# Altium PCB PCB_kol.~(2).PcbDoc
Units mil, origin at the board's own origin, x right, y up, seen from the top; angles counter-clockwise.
Board outline 2952.76 x 2952.76 mil, 4 copper layers (Top Layer, Mid 1 - POWER, Mid 2 - GND, Bottom Layer), stack 61.89 mil thick; 6 components, 16 nets, 136 pads, 7 vias.
Unrouted connection lines stored in the file: 1.
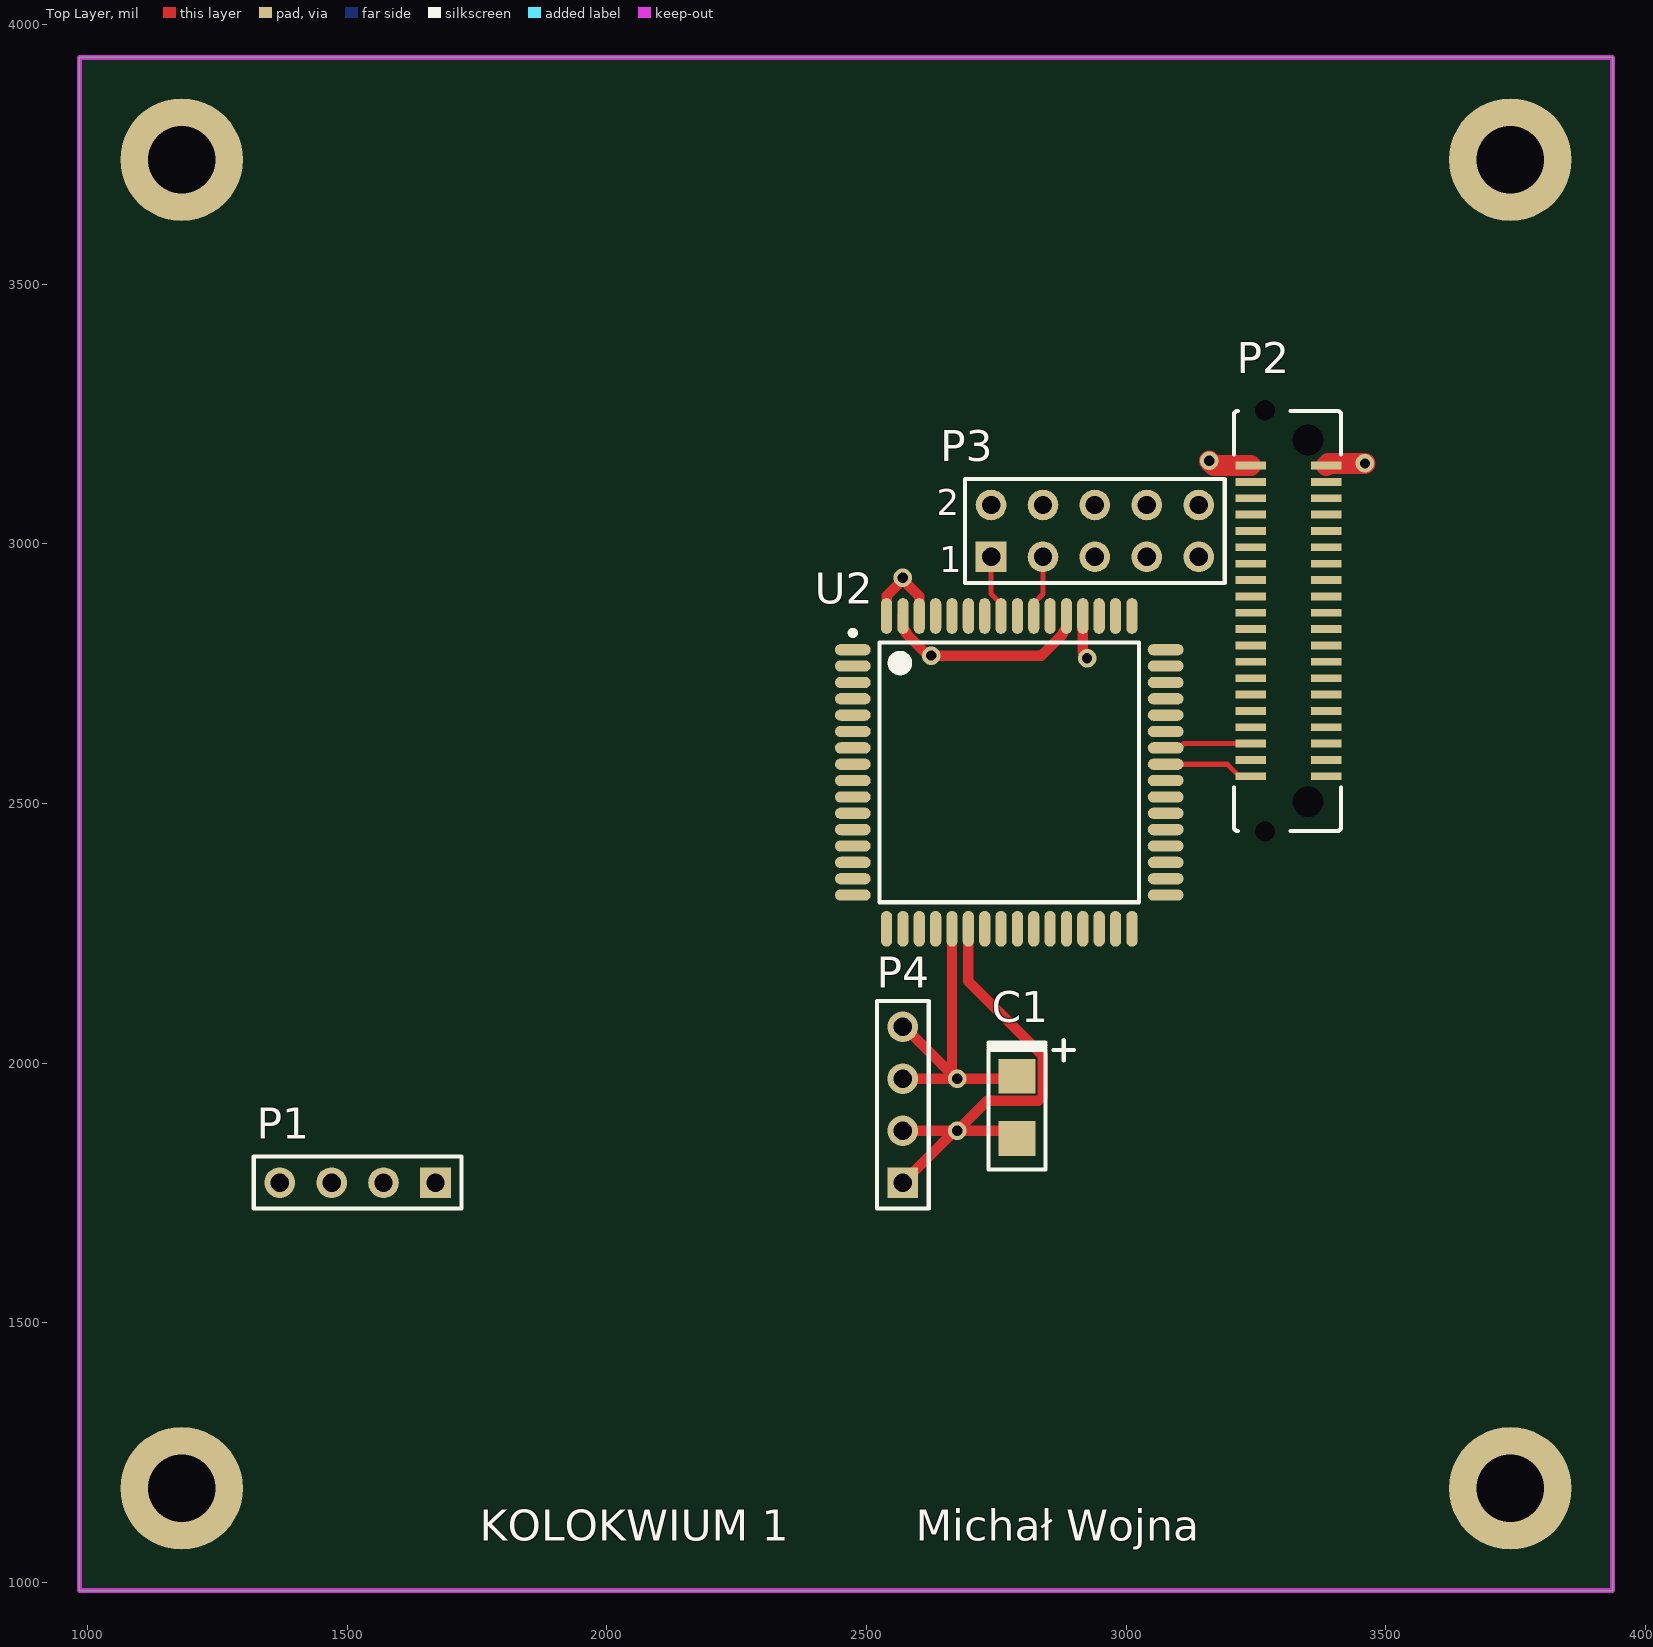
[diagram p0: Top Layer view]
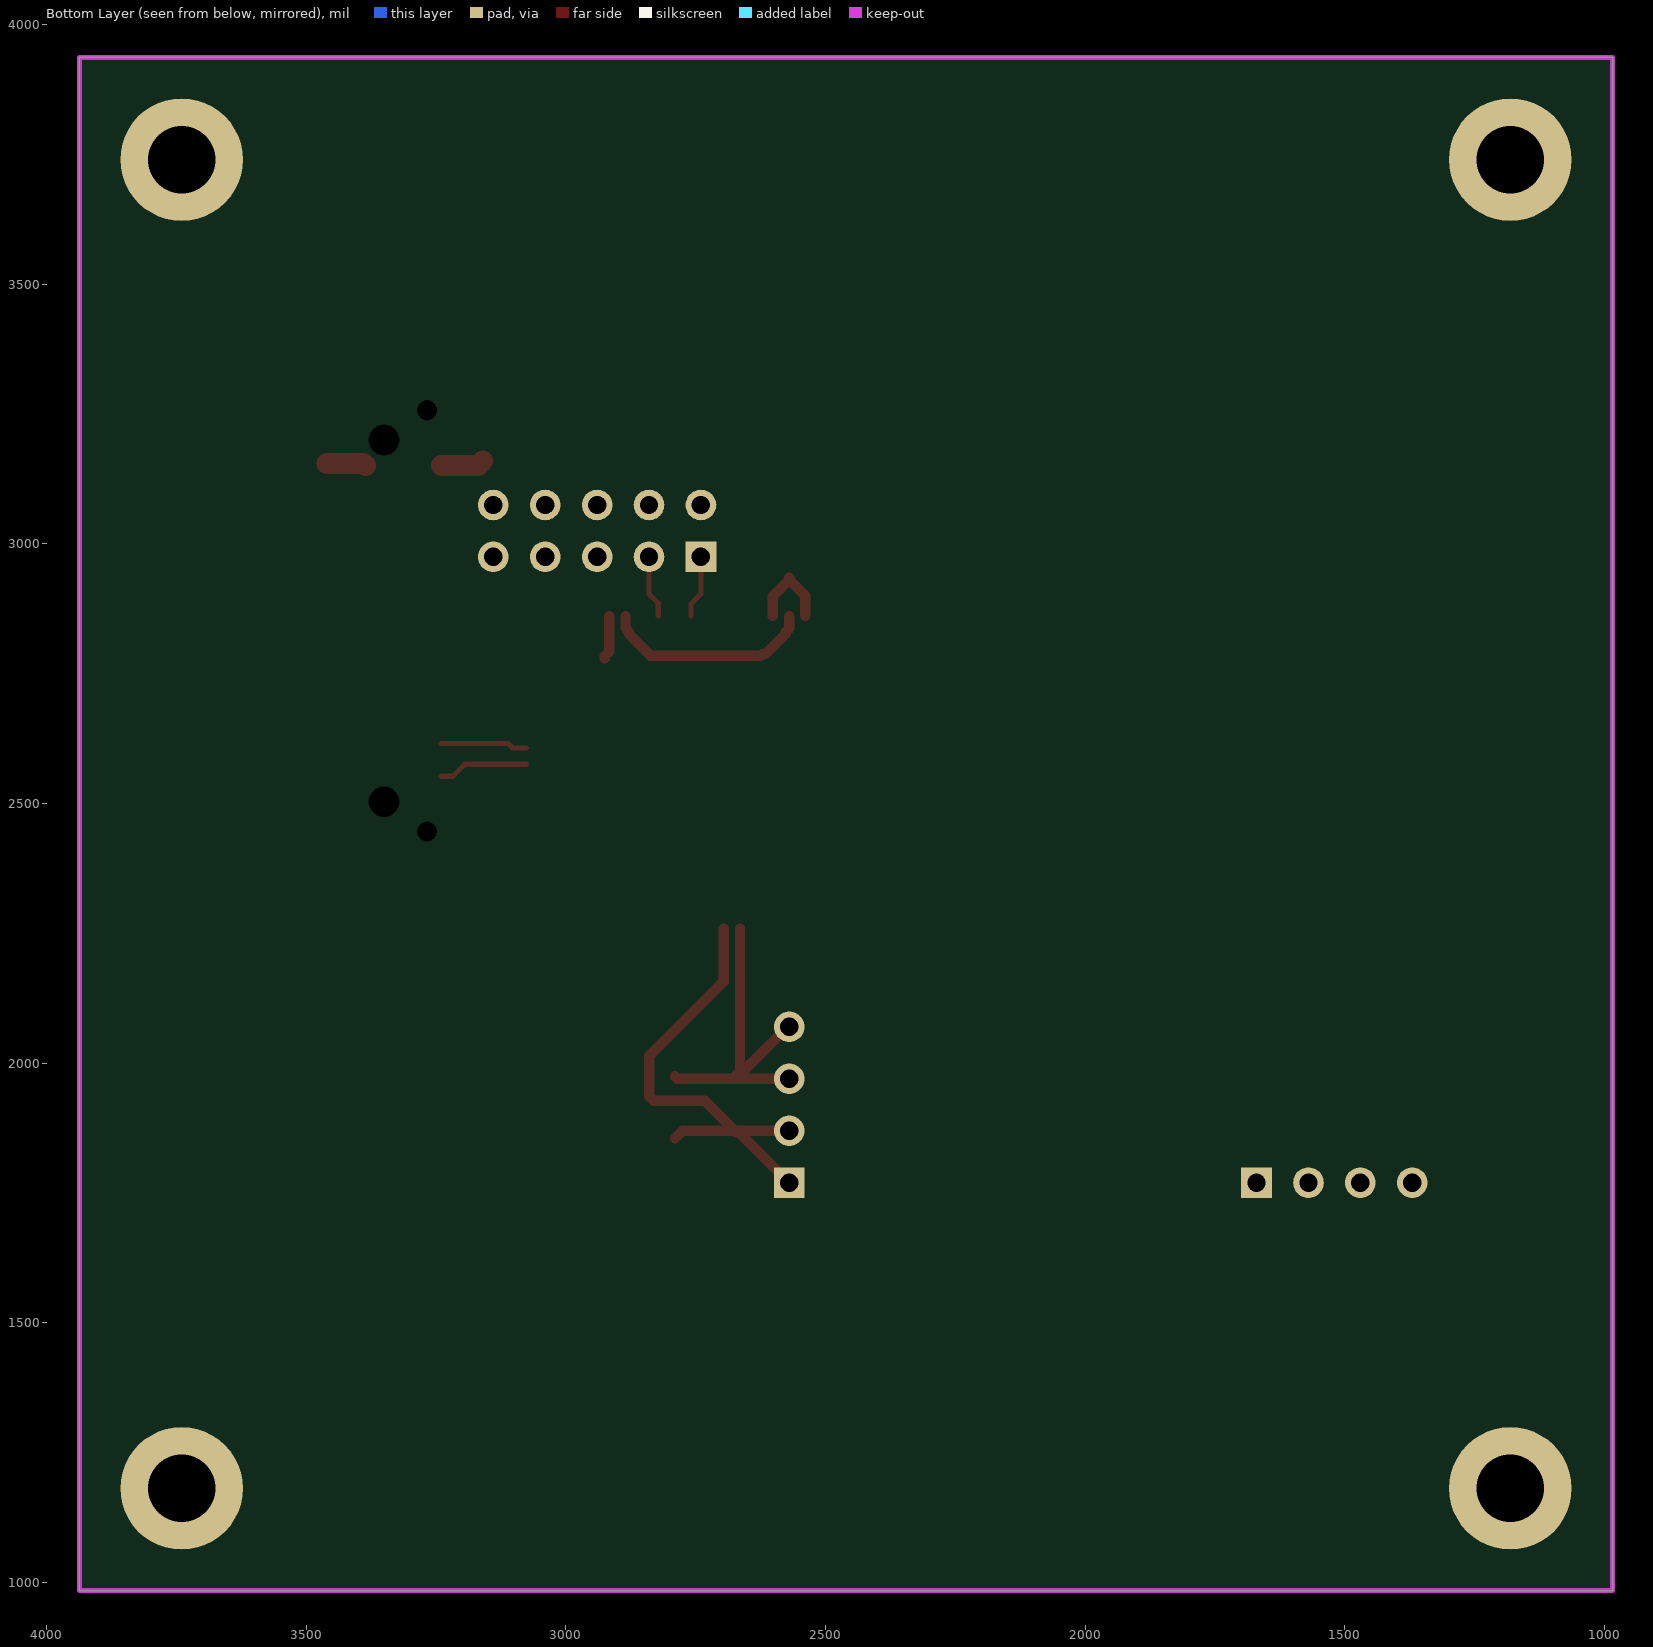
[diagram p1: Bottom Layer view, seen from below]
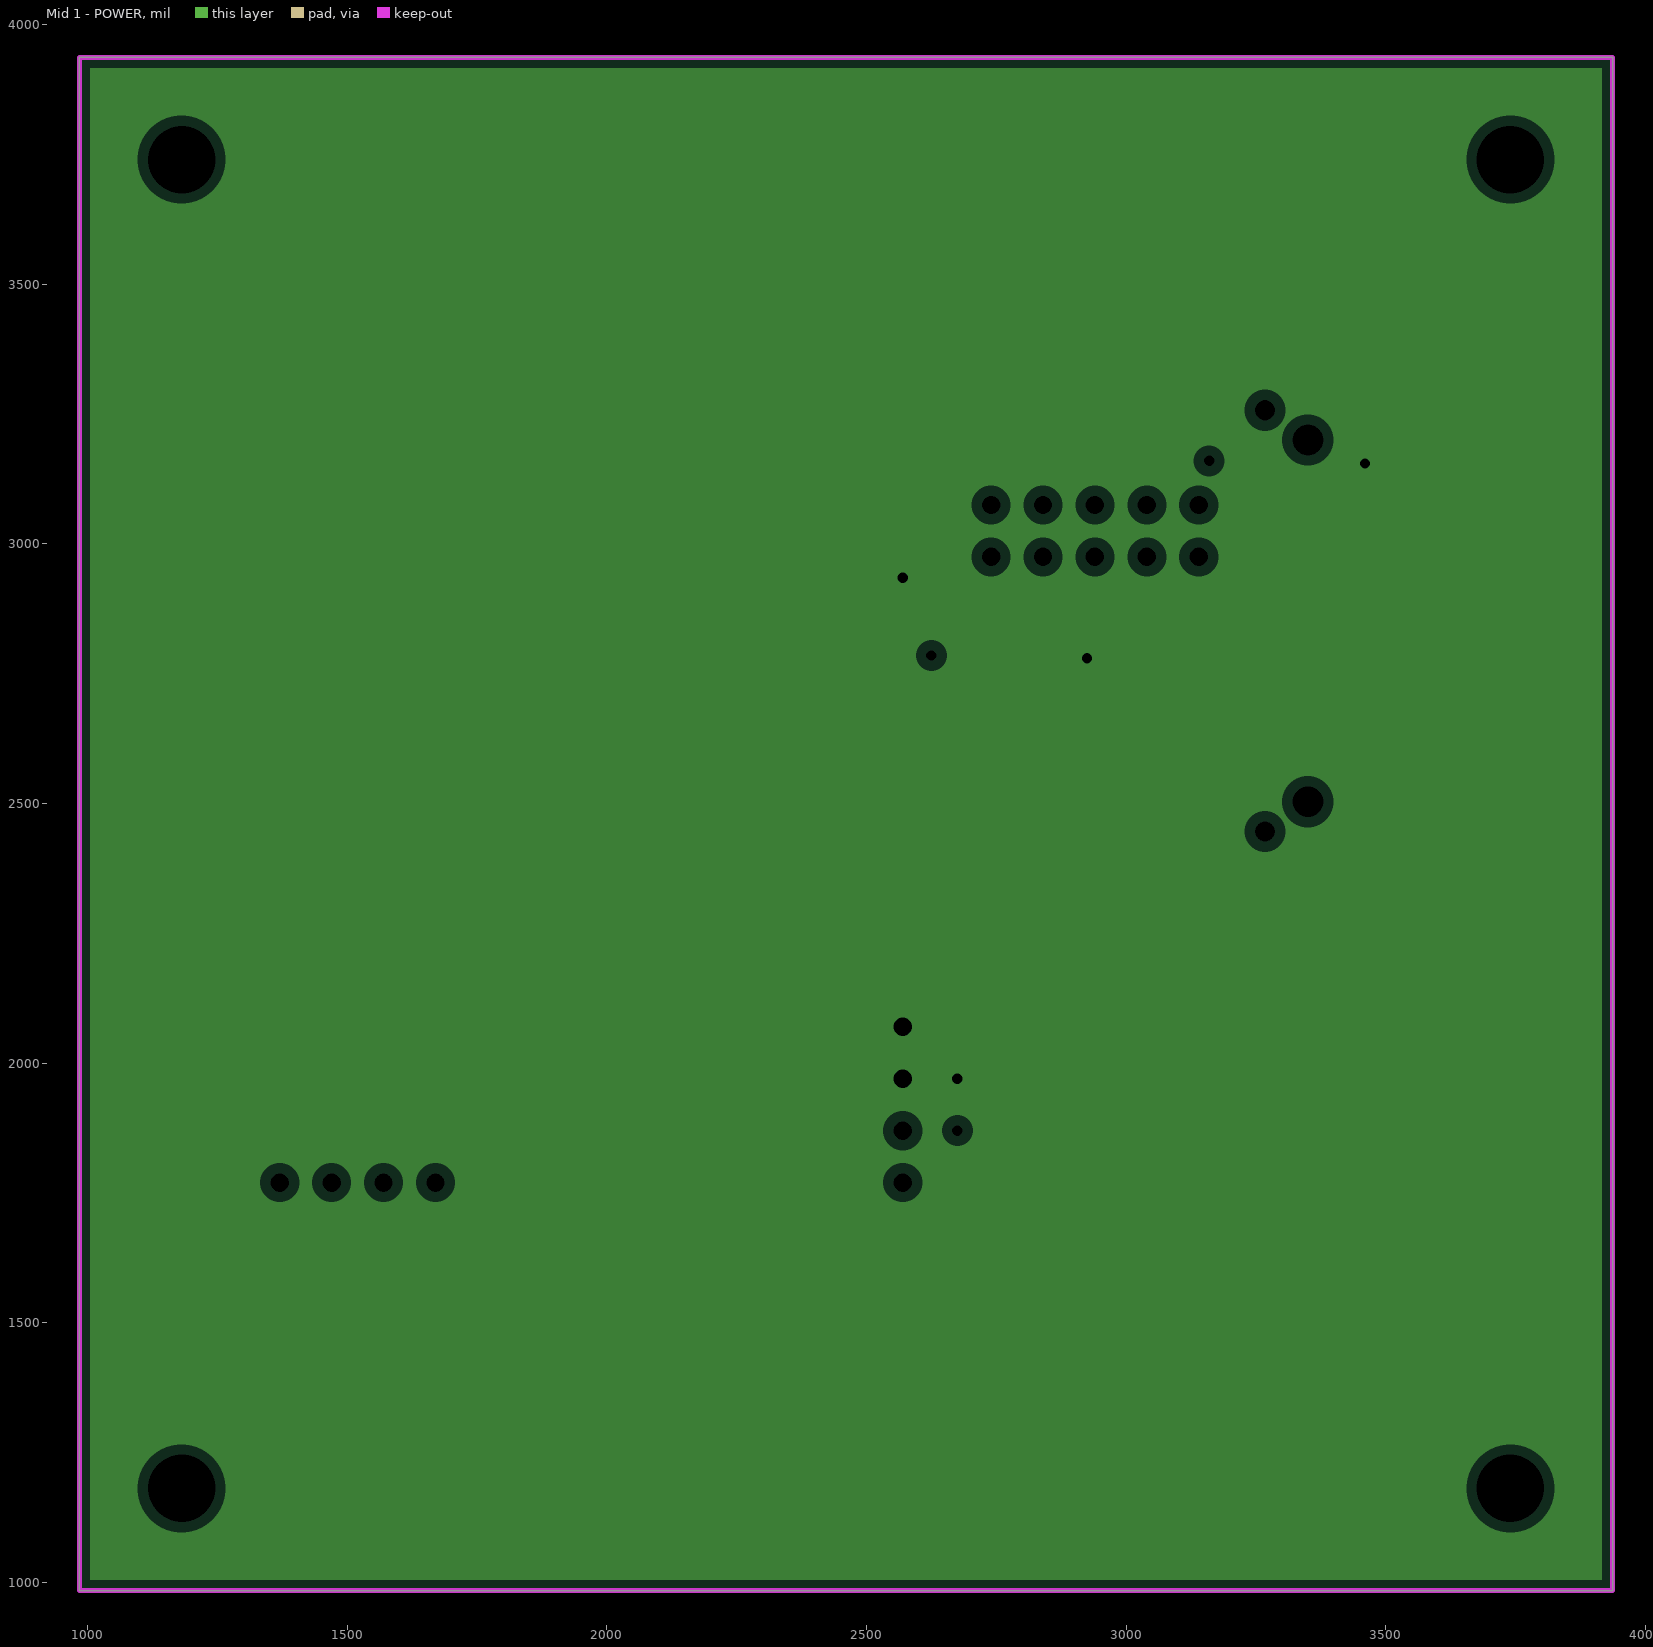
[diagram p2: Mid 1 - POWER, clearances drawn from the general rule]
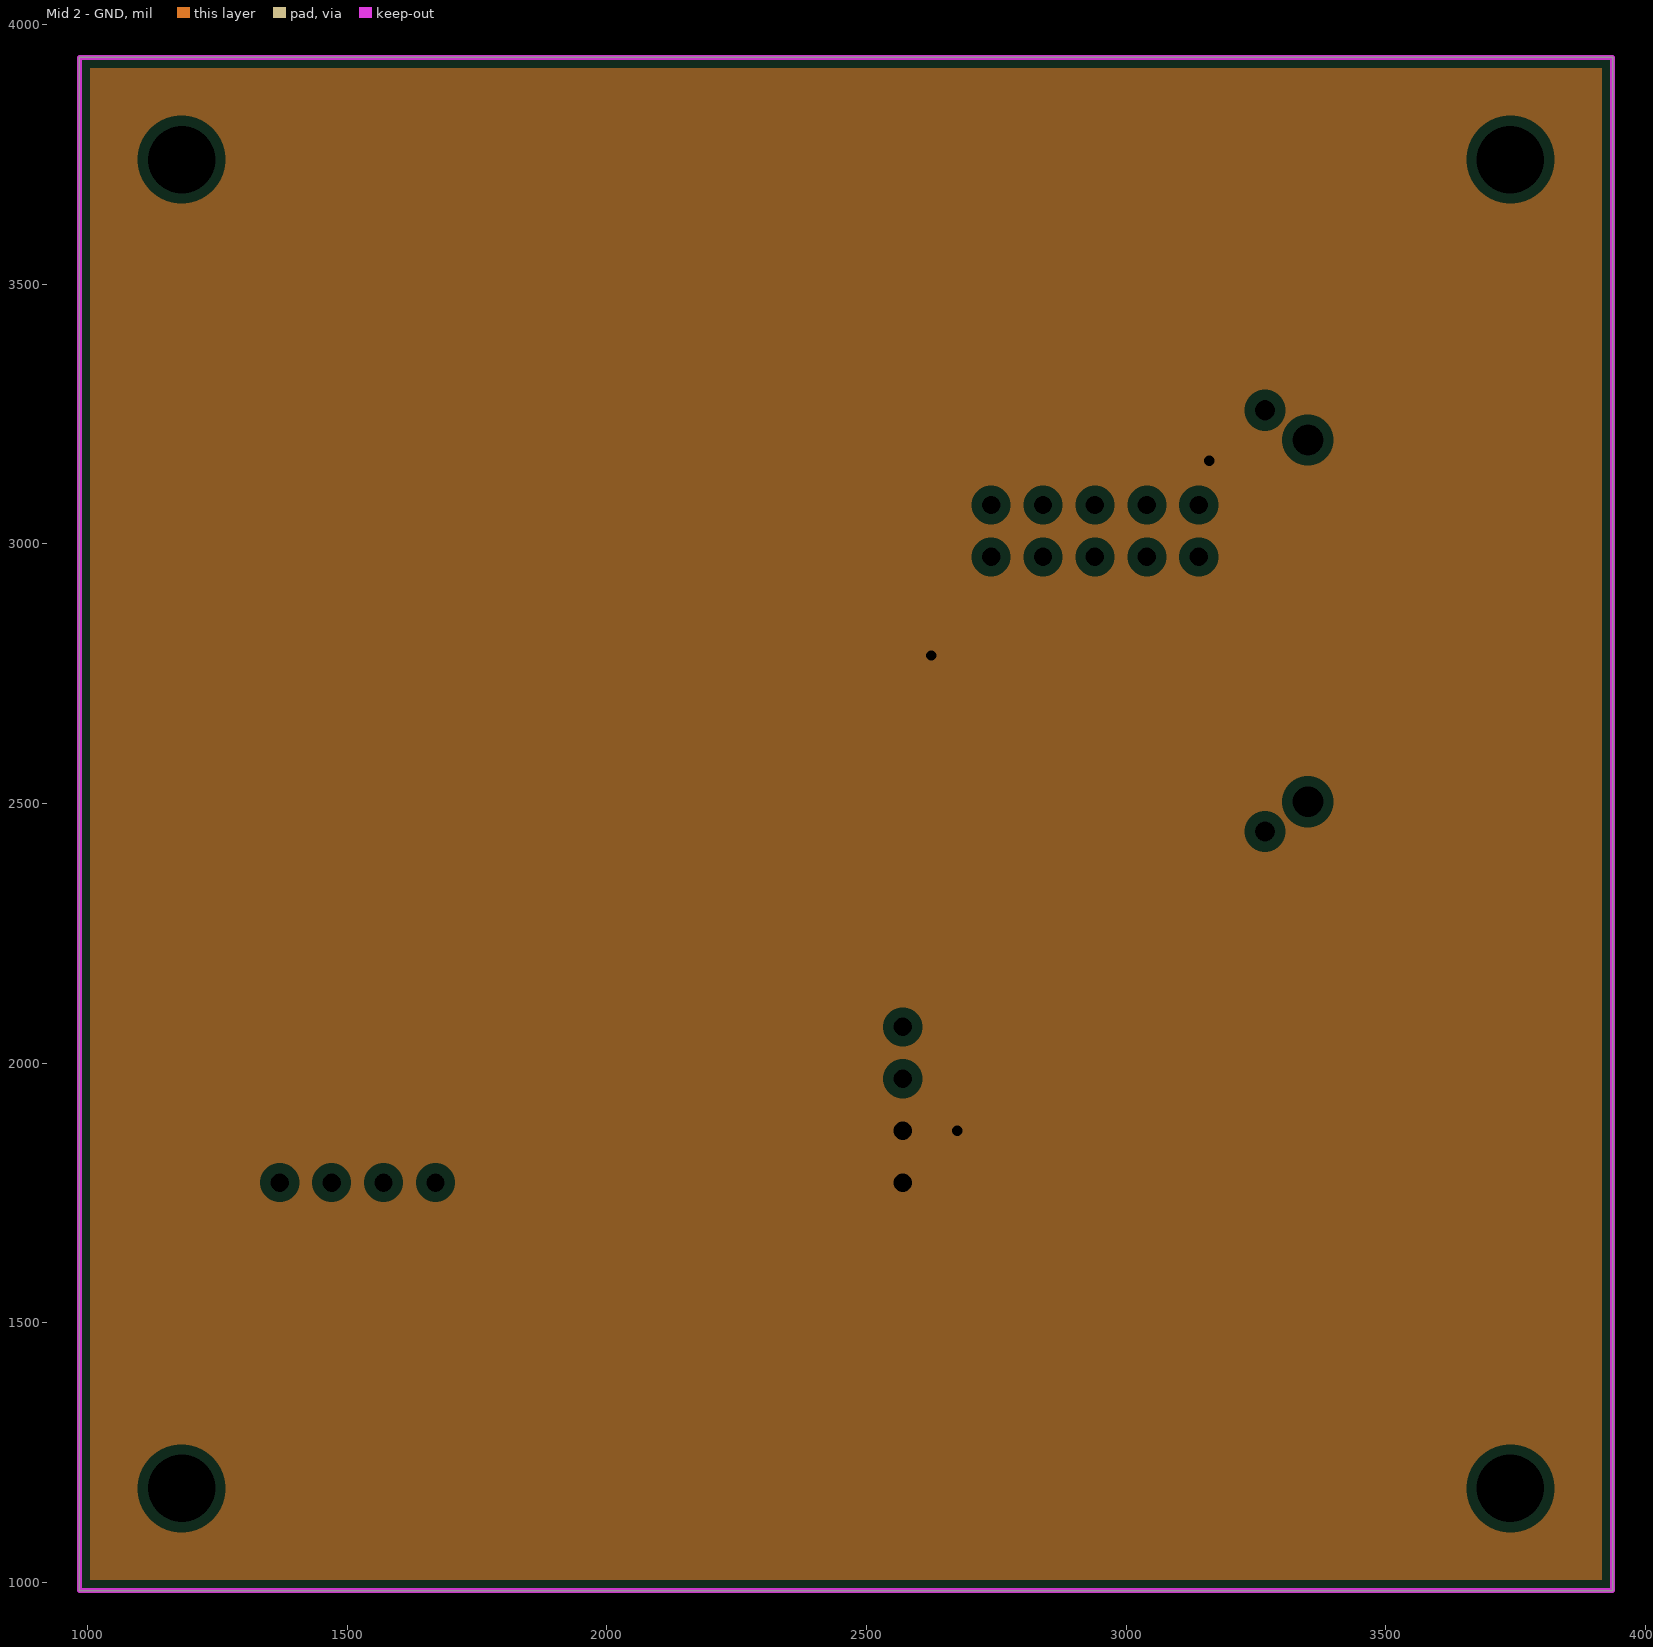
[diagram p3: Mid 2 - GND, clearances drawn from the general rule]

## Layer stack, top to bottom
Top Solder: solder mask 0.4, Solder Resist, Dk 3.5
Top Layer: signal copper 0.7087
Dielectric 1: prepreg 15, Isola DE 104ML, Dk 3.97
Mid 1 - POWER: plane copper 1.378, net 5V0
Dielectric 2: core 27.7165, Isola DE 104ML, Dk 3.97
Mid 2 - GND: plane copper 1.378, net GND
Dielectric 3: prepreg 15, Isola DE 104ML, Dk 3.97
Bottom Layer: signal copper 0.7087
Bottom Solder: solder mask 0.4, Solder Resist, Dk 3.5

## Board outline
984.25,984.25 3937.01,984.25 3937.01,3937.01 984.25,3937.01

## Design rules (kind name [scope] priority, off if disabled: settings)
Clearance [All] p1: gap=4 ignorepadtopadclearanceinfootprint=TRUE
HoleSize [All] p1: absolutevalues=TRUE maxlimit=130 minlimit=1 maxpercent=80.000 minpercent=20.000
MinimumSolderMaskSliver [All] p1: minsoldermaskwidth=4
PlaneClearance [All] p1: clearance=20
PlaneConnect [All] p1: planeconnectstyle=Relief reliefexpansion=20 reliefentries=4 reliefconductorwidth=10 reliefairgap=10
PolygonConnect [All] p1: connectstyle=Relief reliefconductorwidth=10 reliefentries=4 polygonreliefangle="90 Angle" airgapwidth=10
RoutingVias [All] p1: holewidth=28 width=50 viastyle="Through Hole" minholewidth=28 minwidth=50 maxholewidth=28 maxwidth=50
SolderMaskExpansion [All] p1: expansion=2 istentingtop=FALSE
SupplyNets "Schematic Supply Nets_1" [InNet('5V0')] p1: voltage=0.000
SupplyNets "Schematic Supply Nets" [InNet('GND')] p2: voltage=0.000
Width gnd&5v0 [(InNet('5V0') OR InNet('GND'))] p1: maxlimit=100 minlimit=20 preferedwidth=40
Width Width_1 [All] p2: maxlimit=10 minlimit=10 preferedwidth=10
26 further rules are at their usual default settings.

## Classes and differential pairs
component class Schemat_top: P1 P2 P4
component class U_Processor: C1 C? U2

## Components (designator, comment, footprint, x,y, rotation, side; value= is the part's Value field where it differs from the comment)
C1 "22u" VJ_Tantalum_A 2790,1915 r270 top
P1 "Header 4" HDR1X4 1670,1770 r180 top
P2 "SAMTEC LSEM 40-pin" LSEM-120-03.0-L-DV-A-N-K-TR 3312.83,2851.73 r90 top
P3 "Header 5X2" HDR2X5 2740,2975 r0 top
P4 "Header 4" HDR1X4 2570,1770 r90 top
U2 "ATmega128-16AU" 64A_N 2775,2560 r0 top

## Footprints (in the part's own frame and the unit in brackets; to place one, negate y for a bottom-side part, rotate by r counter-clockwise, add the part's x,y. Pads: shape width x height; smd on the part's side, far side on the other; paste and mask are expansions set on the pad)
64A_N [mm] "Thin QFP, 64-Leads, Body 14x14mm, Pitch 0.8mm, IPC Medium Density"
  oval 1.75x0.55 smd: 1(-7.65,6) 2(-7.65,5.2) 3(-7.65,4.4) 4(-7.65,3.6) 5(-7.65,2.8) 6(-7.65,2) 7(-7.65,1.2) 8(-7.65,0.4) 9(-7.65,-0.4) 10(-7.65,-1.2) 11(-7.65,-2) 12(-7.65,-2.8) 13(-7.65,-3.6) 14(-7.65,-4.4) 15(-7.65,-5.2) 16(-7.65,-6) 33(7.65,-6) 34(7.65,-5.2) 35(7.65,-4.4) 36(7.65,-3.6) 37(7.65,-2.8) 38(7.65,-2) 39(7.65,-1.2) 40(7.65,-0.4) 41(7.65,0.4) 42(7.65,1.2) 43(7.65,2) 44(7.65,2.8) 45(7.65,3.6) 46(7.65,4.4) 47(7.65,5.2) 48(7.65,6)
  oval 0.55x1.75 smd: 17(-6,-7.65) 18(-5.2,-7.65) 19(-4.4,-7.65) 20(-3.6,-7.65) 21(-2.8,-7.65) 22(-2,-7.65) 23(-1.2,-7.65) 24(-0.4,-7.65) 25(0.4,-7.65) 26(1.2,-7.65) 27(2,-7.65) 28(2.8,-7.65) 29(3.6,-7.65) 30(4.4,-7.65) 31(5.2,-7.65) 32(6,-7.65) 49(6,7.65) 50(5.2,7.65) 51(4.4,7.65) 52(3.6,7.65) 53(2.8,7.65) 54(2,7.65) 55(1.2,7.65) 56(0.4,7.65) 57(-0.4,7.65) 58(-1.2,7.65) 59(-2,7.65) 60(-2.8,7.65) 61(-3.6,7.65) 62(-4.4,7.65) 63(-5.2,7.65) 64(-6,7.65)
  silkscreen extent -7.77,-6.35 6.35,6.95, body extent -7,-7 7,7, height 1.2
HDR1X4 [mm] "Connector; Header; 4 Position"
  rect 1.5x1.5 hole 0.9: 1(0,0)
  round 1.5 hole 0.9: 2(2.54,0) 3(5.08,0) 4(7.62,0)
  silkscreen extent -1.27,-1.27 8.89,1.27
HDR2X5 [mm] "Connector; Header; 5x2 Position"
  rect 1.5x1.5 hole 0.9: 1(0,0)
  round 1.5 hole 0.9: 2(0,2.54) 3(2.54,0) 4(2.54,2.54) 5(5.08,0) 6(5.08,2.54) 7(7.62,0) 8(7.62,2.54) 9(10.16,0) 10(10.16,2.54)
  silkscreen extent -1.27,-1.27 11.43,3.81
LSEM-120-03.0-L-DV-A-N-K-TR [mm] "LSEM 0.8mm Razor Beam Hermaphroditic Connector 40-pin"
  round 0 hole 1 unplated: 0(-10.3,1.15) 0(10.3,1.15)
  round 2 on Top Paste paste+2: 0(-10.3,1.15) 0(10.3,1.15)
  round 2.1 on Top Solder paste+2: 0(-10.3,1.15) 0(10.3,1.15)
  round 0 hole 1.5 unplated: 0(-8.85,-0.95) 0(8.85,-0.95)
  rect 0.38x1.5 smd: 1(7.6,-1.85) 2(7.6,1.85) 3(6.8,-1.85) 4(6.8,1.85) 5(6,-1.85) 6(6,1.85) 7(5.2,-1.85) 8(5.2,1.85) 9(4.4,-1.85) 10(4.4,1.85) 11(3.6,-1.85) 12(3.6,1.85) 13(2.8,-1.85) 14(2.8,1.85) 15(2,-1.85) 16(2,1.85) 17(1.2,-1.85) 18(1.2,1.85) 19(0.4,-1.85) 20(0.4,1.85) 21(-0.4,-1.85) 22(-0.4,1.85) 23(-1.2,-1.85) 24(-1.2,1.85) 25(-2,-1.85) 26(-2,1.85) 27(-2.8,-1.85) 28(-2.8,1.85) 29(-3.6,-1.85) 30(-3.6,1.85) 31(-4.4,-1.85) 32(-4.4,1.85) 33(-5.2,-1.85) 34(-5.2,1.85) 35(-6,-1.85) 36(-6,1.85) 37(-6.8,-1.85) 38(-6.8,1.85) 39(-7.6,-1.85) 40(-7.6,1.85)
  silkscreen extent -10.28,-2.57 10.28,2.68, body extent -10.2,-2.7 10.2,2.8, height 4.58
VJ_Tantalum_A [mm]
  rect 1.7x1.8 smd: 1(-1.525,0) 2(1.525,0)
  silkscreen extent -3.3,-1.4 3.05,2.79, body extent -1.85,-0.89 1.85,0.89, height 1.6

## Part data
C1: library part Capacitor_polarized, Manufacturer=VJ, Part Number=293D223X9016D2TE3, Rated Voltage=16V, Tolerance=10%
P1 P4: "Header, 4-Pin"
P2: "Component desciption", Manufacture=SAMTEC, Part Number=LSEM-120-03.0-L-DV-A-N-K-TR, Supplier Part Number 1=2433813
P3: "Header, 5-Pin, Dual row"
U2: "8-bit AVR Microcontroller, 4.5-5.5V, 128KB Flash, 4KB EEPROM, 4KB SRAM, 64-pin TQFP, Industrial Grade (-40°C to 85°C)"

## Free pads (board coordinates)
  round 236.22 hole 129.92: 0(1181.1,1181.1) 0(1181.1,3740.16) 0(3740.16,1181.1) 0(3740.16,3740.16)

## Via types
v1: diameter 35.43, hole 19.68, Top Layer to Mid 1 - POWER, tented both sides, 4 vias
v2: diameter 35.43, hole 19.68, Top Layer to Mid 2 - GND, tented both sides, 3 vias

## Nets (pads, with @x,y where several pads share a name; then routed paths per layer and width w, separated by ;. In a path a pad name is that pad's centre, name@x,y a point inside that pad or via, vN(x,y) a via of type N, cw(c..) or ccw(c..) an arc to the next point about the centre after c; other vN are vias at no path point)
5V0: C1.1 P2.1 P4.3 P4.4 U2.21 U2.52 U2.62 U2.64 | length 989.2
  Top Layer w20: U2.64 2539.1,2861.5 2539.1,2899.92 v1@2570,2930.82 ; P4.3 v1@2672.5,1970 ; P4.4 2572.5,2070 v1@2672.5,1970 ; v1(2570,2935) v1@2570,2930.82 ; U2.62 2601.46,2861.5 2601.46,2899.37 v1@2570,2930.82 ; U2.21 2664.76,1984.41 2675,1974.18 v1(2675,1970) ; C1.1 2784.96,1970 v1(2675,1970) ; U2.52 2916.73,2792.44 2925,2784.18 v1(2925,2780) ; v1@2672.5,1970 v1(2675,1970)
  Top Layer w40: P2.1 3389.72,3155 v1(3460,3155)
BUS1: U2.51
BUS2: U2.50
BUS3: U2.49
BUS4: U2.47 U2.48
BUS5: U2.46
BUS6: U2.45
BUS7: U2.44
GND: C1.2 P2.2 P4.1 P4.2 U2.22 U2.53 U2.63 | length 1440.4
  Top Layer w20: P4.1 2667.05,1867.05 2672.05,1867.05 v2(2675,1870) ; P4.2 v2(2675,1870) ; U2.63 2570.28,2837.11 2576.95,2830.44 2576.95,2827.28 2616.27,2787.95 2622.05,2787.95 v2(2625,2785) 2836.29,2785 2878.57,2827.28 2878.57,2830.44 2885.24,2837.11 U2.53 ; U2.22 2696.26,2157.48 2839.43,2014.3 2839.43,1935.78 2831.23,1927.57 2732.57,1927.57 v2(2675,1870) ; C1.2 2774.96,1870 v2(2675,1870)
  Top Layer w40: v2(3160,3160) 3169.06,3150.94 P2.2
out1: P2.40 U2.41 | length 173.4
  Top Layer w10: U2.41 3194.72,2575.75 3217.95,2552.52 P2.40
out2: P2.36 U2.42 | length 167.2
  Top Layer w10: U2.42 3102.96,2607.24 3111.22,2615.51 P2.36
RESET: U2.20
TCK: P3.1 U2.57 | length 121.8
  Top Layer w10: P3.1 2740,2904.06 2759.25,2884.8 U2.57
TDI: U2.54
TDO: P3.3 U2.55 | length 121.2
  Top Layer w10: U2.55 2822.24,2885.82 2840,2903.57 P3.3
TMS: U2.56
pads on no net: P1.1 P1.2 P1.3 P1.4 P2.0 P2.3 P2.4 P2.5 P2.6 P2.7 P2.8 P2.9 P2.10 P2.11 P2.12 P2.13 P2.14 P2.15 P2.16 P2.17 P2.18 P2.19 P2.20 P2.21 P2.22 P2.23 P2.24 P2.25 P2.26 P2.27 P2.28 P2.29 P2.30 P2.31 P2.32 P2.33 P2.34 P2.35 P2.37 P2.38 P2.39 P3.2 P3.4 P3.5 P3.6 P3.7 P3.8 P3.9 P3.10 U2.1 U2.2 U2.3 U2.4 U2.5 U2.6 U2.7 U2.8 U2.9 U2.10 U2.11 U2.12 U2.13 U2.14 U2.15 U2.16 U2.17 U2.18 U2.19 U2.23 U2.24 U2.25 U2.26 U2.27 U2.28 U2.29 U2.30 U2.31 U2.32 U2.33 U2.34 U2.35 U2.36 U2.37 U2.38 U2.39 U2.40 U2.43 U2.58 U2.59 U2.60 U2.61

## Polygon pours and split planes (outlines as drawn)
5V0 on Mid 1 - POWER (split plane): 3916.91,1004.35 1004.35,1004.35 1004.35,3916.91 3916.91,3916.91
GND on Mid 2 - GND (split plane): 3916.91,1004.35 1004.35,1004.35 1004.35,3916.91 3916.91,3916.91

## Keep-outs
Keep-Out Layer:
  the board outline again, w10

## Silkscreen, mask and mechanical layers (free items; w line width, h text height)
Top Overlay:
  text "KOLOKWIUM 1" at 1755,1080 h60
  text "Michał Wojna" at 2595,1080 h60

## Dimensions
1181.1,3740.16 to 3740.16,3740.16 on M5 Dimensions
3937.01,984.25 to 3937.01,3937.01 on M5 Dimensions
984.25,984.25 to 3937.01,984.25 on M5 Dimensions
